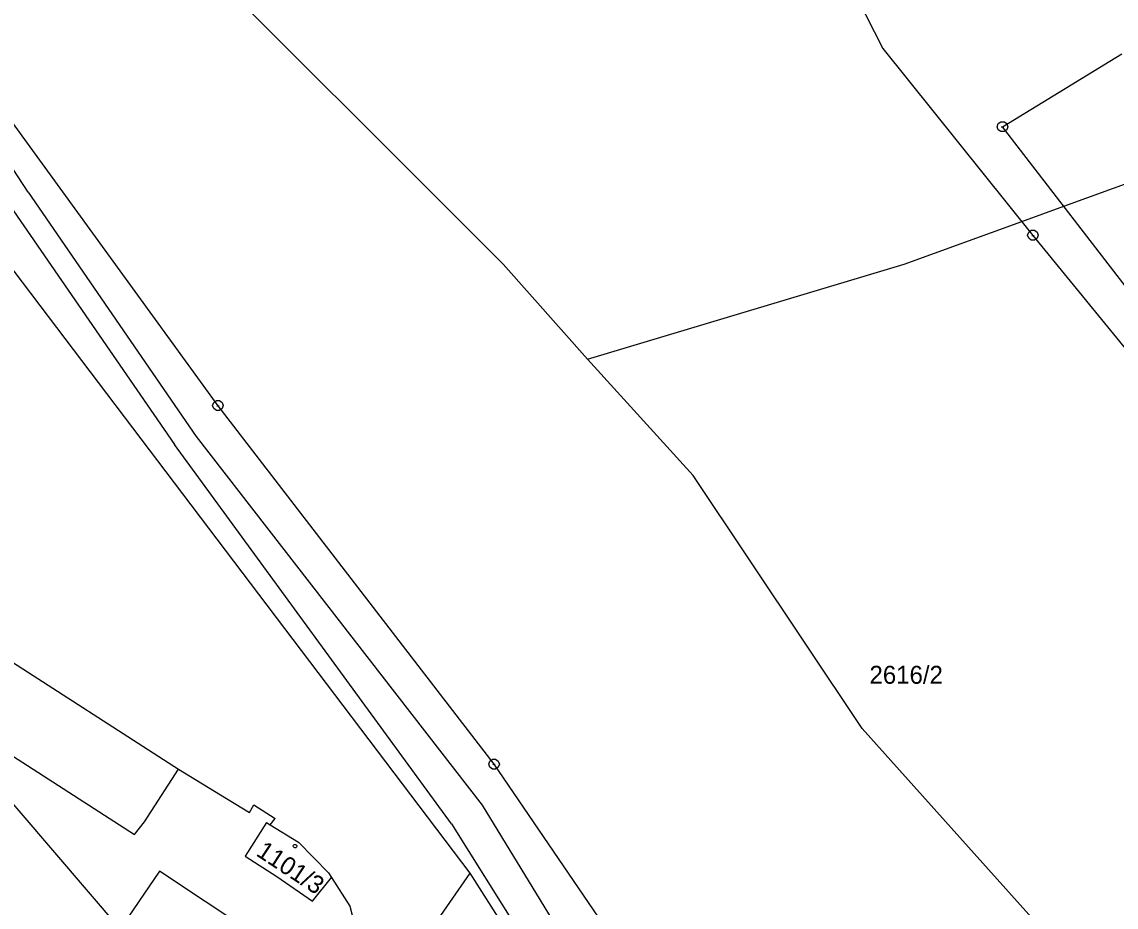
# Model space of a CAD drawing. Extents: x -806774 to -803680, y -1151731 to -1150053.
# Drawn here: x -804078.6 to -803974.9, y -1150361.4 to -1150277.5 of the extents above; entities that cross this region are included whole.
import ezdxf

# ---------------------------------------------------------------- set-up
doc = ezdxf.new("R2010")
doc.units = 0
for name, color, linetype in [('1', 7, 'Continuous'), ('11', 7, 'Continuous'), ('12', 7, 'Continuous'), ('2', 7, 'Continuous'), ('4', 7, 'Continuous'), ('5', 7, 'Continuous'), ('8', 7, 'Continuous')]:
    doc.layers.add(name, color=color, linetype=linetype)

msp = doc.modelspace()

# ---------------------------------------------------------------- linework, layer by layer
at = {"layer": '1'}
for p, q in [((-804009.55, -1150255.32), (-803997.02, -1150280.06)), ((-804036.11, -1150358.19), (-804098.91, -1150275.35)), ((-803997.02, -1150280.06), (-803982.8, -1150297.76)), ((-803985.68, -1150287.47), (-803974.38, -1150280.55)), ((-804060.01, -1150313.9), (-804081.21, -1150284.7)), ((-803936.41, -1150351.52), (-803985.68, -1150287.47)), ((-803982.8, -1150297.76), (-803972.77, -1150310.06)), ((-804033.86, -1150347.88), (-804060.01, -1150313.9)), ((-804114.51, -1150324.58), (-804067.92, -1150354.52)), ((-804086.7, -1150333.56), (-804063.77, -1150348.34)), ((-804004.05, -1150391.51), (-804033.86, -1150347.88)), ((-804066.98, -1150353.34), (-804063.77, -1150348.34)), ((-804063.77, -1150348.34), (-804059.77, -1150350.77)), ((-804059.77, -1150350.77), (-804057.02, -1150352.44)), ((-804057.02, -1150352.44), (-804056.61, -1150351.71)), ((-804056.61, -1150351.71), (-804054.61, -1150353.01)), ((-804067.92, -1150354.52), (-804066.98, -1150353.34)), ((-804055.41, -1150353.41), (-804057.43, -1150356.6)), ((-804055.41, -1150353.41), (-804055.07, -1150353.62)), ((-804055.07, -1150353.62), (-804054.61, -1150353.01)), ((-804055.07, -1150353.62), (-804052.39, -1150355.25)), ((-804049.55, -1150358.18), (-804052.39, -1150355.25)), ((-804057.43, -1150356.6), (-804054.44, -1150358.5)), ((-804065.57, -1150358), (-804070.4, -1150365.1)), ((-804048.65, -1150369.22), (-804065.57, -1150358)), ((-804054.44, -1150358.5), (-804051.06, -1150360.86)), ((-804049.55, -1150358.18), (-804049.27, -1150358.61)), ((-804042.43, -1150367.25), (-804036.11, -1150358.19)), ((-804019.43, -1150384.54), (-804036.11, -1150358.19)), ((-804051.06, -1150360.86), (-804049.27, -1150358.61)), ((-804049.27, -1150358.61), (-804047.52, -1150361.32)), ((-804047.52, -1150361.32), (-804046.65, -1150364.68))]:
    msp.add_line(p, q, dxfattribs=at)
at = {"layer": '11'}
for points in [[(-804025, -1150309.5), (-803995, -1150300.5), (-803983.85, -1150296.45), (-803979.88, -1150295), (-803973, -1150292.5), (-803959, -1150285.5), (-803958.91, -1150285.16), (-803957.26, -1150278.83), (-803954.65, -1150268.82), (-803953, -1150262.5), (-803939, -1150245.5), (-803938.23, -1150243.8), (-803935.53, -1150237.88), (-803929, -1150223.5)], [(-804025, -1150309.5), (-804033, -1150300.5), (-804065, -1150268.5), (-804075, -1150250.5)], [(-803889.5, -1150497.5), (-803923, -1150445.5), (-803947, -1150402.5), (-803999, -1150344.5), (-804015, -1150320.5), (-804025, -1150309.5)], [(-804088.1, -1150341.55), (-804069.3, -1150363.48), (-804065, -1150368.5), (-804054.39, -1150378.78), (-804033, -1150399.5), (-804030.88, -1150402.01), (-804030.78, -1150402.13), (-804001, -1150437.5), (-803998.96, -1150441.11), (-803986.34, -1150463.47), (-803955, -1150519), (-803948.96, -1150540.6), (-803948.43, -1150542.51), (-803945.88, -1150551.64), (-803944.24, -1150557.49), (-803942, -1150565.5), (-803941.8, -1150586.17), (-803941.67, -1150599.56), (-803941.67, -1150599.64), (-803941.5, -1150617.26), (-803944.75, -1150646.55), (-803952.79, -1150686.98), (-803960.74, -1150712.66)]]:
    msp.add_lwpolyline(points, dxfattribs=at)
at = {"layer": '12'}
for p, q in [((-804055.41, -1150353.41), (-804057.43, -1150356.6)), ((-804055.41, -1150353.41), (-804055.07, -1150353.62)), ((-804055.07, -1150353.62), (-804052.39, -1150355.25)), ((-804049.55, -1150358.18), (-804052.39, -1150355.25)), ((-804057.43, -1150356.6), (-804054.44, -1150358.5)), ((-804065.57, -1150358), (-804070.4, -1150365.1)), ((-804048.65, -1150369.22), (-804065.57, -1150358)), ((-804054.44, -1150358.5), (-804051.06, -1150360.86)), ((-804049.55, -1150358.18), (-804049.27, -1150358.61)), ((-804051.06, -1150360.86), (-804049.27, -1150358.61))]:
    msp.add_line(p, q, dxfattribs=at)
at = {"layer": '4'}
for p, q in [((-804077.99, -1150293.67), (-804083.56, -1150285.18)), ((-804080.36, -1150294), (-804064.13, -1150317.57)), ((-804077.99, -1150293.67), (-804062.09, -1150316.83)), ((-804062.09, -1150316.83), (-804034.98, -1150351.76)), ((-804037.88, -1150353.52), (-804064.13, -1150317.57)), ((-804034.98, -1150351.76), (-804017.28, -1150380.76)), ((-804037.88, -1150353.52), (-804018.99, -1150383.74))]:
    msp.add_line(p, q, dxfattribs=at)
at = {"layer": '5'}
msp.add_lwpolyline([(-804052.62, -1150355.5), (-804052.54, -1150355.57), (-804052.55, -1150355.67), (-804052.57, -1150355.73), (-804052.63, -1150355.8), (-804052.74, -1150355.81), (-804052.8, -1150355.78), (-804052.86, -1150355.71), (-804052.88, -1150355.62), (-804052.85, -1150355.55), (-804052.79, -1150355.48), (-804052.68, -1150355.47)], close=True, dxfattribs=at)
at = {"layer": '8'}
for p, q in [((-803985.8, -1150287.47), (-803985.56, -1150287.47)), ((-803982.92, -1150297.76), (-803982.68, -1150297.76)), ((-804060.13, -1150313.9), (-804059.89, -1150313.9)), ((-804033.98, -1150347.88), (-804033.74, -1150347.88))]:
    msp.add_line(p, q, dxfattribs=at)
for points in [[(-803985.53, -1150286.99), (-803985.28, -1150287.17), (-803985.18, -1150287.46), (-803985.28, -1150287.75), (-803985.53, -1150287.93), (-803985.84, -1150287.93), (-803986.09, -1150287.75), (-803986.19, -1150287.46), (-803986.09, -1150287.17), (-803985.84, -1150286.99)], [(-803982.65, -1150297.28), (-803982.4, -1150297.46), (-803982.3, -1150297.75), (-803982.4, -1150298.04), (-803982.65, -1150298.22), (-803982.96, -1150298.22), (-803983.21, -1150298.04), (-803983.31, -1150297.75), (-803983.21, -1150297.46), (-803982.96, -1150297.28)], [(-804059.86, -1150313.42), (-804059.61, -1150313.6), (-804059.51, -1150313.89), (-804059.61, -1150314.18), (-804059.86, -1150314.36), (-804060.17, -1150314.36), (-804060.42, -1150314.18), (-804060.52, -1150313.89), (-804060.42, -1150313.6), (-804060.17, -1150313.42)], [(-804033.71, -1150347.4), (-804033.46, -1150347.58), (-804033.36, -1150347.87), (-804033.46, -1150348.16), (-804033.71, -1150348.34), (-804034.02, -1150348.34), (-804034.27, -1150348.16), (-804034.37, -1150347.87), (-804034.27, -1150347.58), (-804034.02, -1150347.4)]]:
    msp.add_lwpolyline(points, close=True, dxfattribs=at)

# ---------------------------------------------------------------- texts
at = {"layer": '2'}
msp.add_text('2616/2', height=1.7, dxfattribs=at).set_placement((-803998.29, -1150340.25))
msp.add_text('1101/3', height=1.7, rotation=326.7005, dxfattribs=at).set_placement((-804056.5, -1150356.47))

doc.saveas('drawing.dxf')
